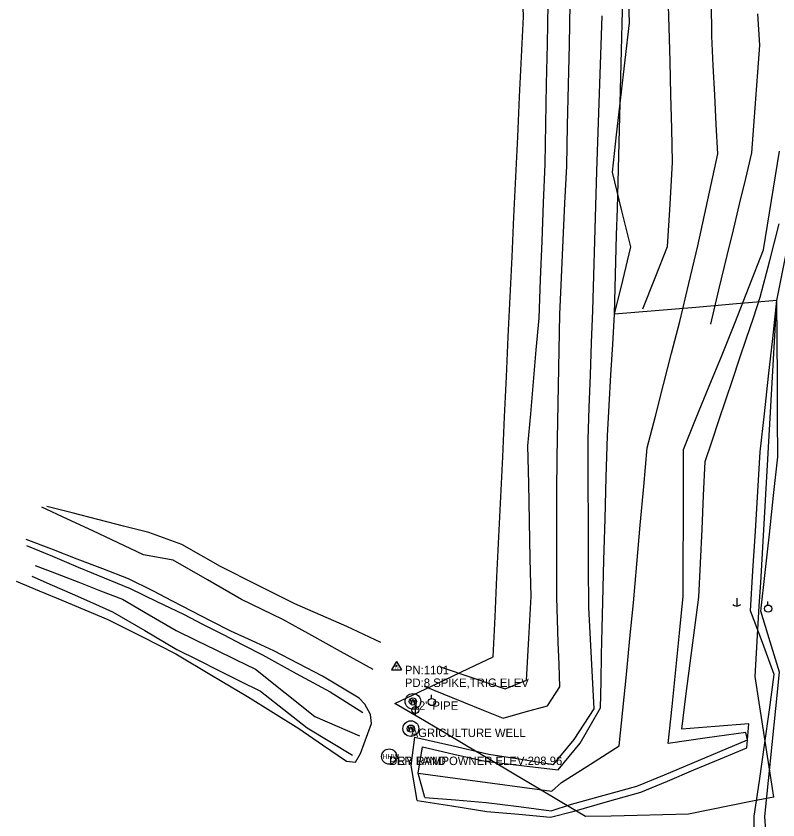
# Model space of a CAD drawing. Extents: x 1445297 to 1476720, y 2042269 to 2057889.
# Drawn here: x 1445590.2 to 1446040.2, y 2043652.1 to 2044126.9 of the extents above; entities that cross this region are included whole.
import ezdxf

# ---------------------------------------------------------------- set-up
doc = ezdxf.new("R2010")
doc.units = 0
for name, color, linetype in [('S_DITCHLINE', 7, 'Continuous'), ('S_HIST_HIGH_WATER', 7, 'Continuous'), ('S_HIST_HIGH_WATER_ANNOT', 7, 'Continuous'), ('S_LEVEE', 7, 'Continuous'), ('S_MSC_PT_SYM', 7, 'Continuous'), ('S_SECONDARY_CTL', 7, 'Continuous'), ('S_SECONDARY_CTL_ANNOT', 7, 'Continuous'), ('S_STREAM', 7, 'Continuous'), ('S_SURVEY_TEXT_ANNOT', 7, 'Continuous'), ('S_TREE', 7, 'Continuous'), ('S_UTILITY_POLE', 7, 'Continuous'), ('S_WATER_WELL', 7, 'Continuous'), ('S_WATER_WELL_ANNOT', 7, 'Continuous')]:
    doc.layers.add(name, color=color, linetype=linetype)

msp = doc.modelspace()

# ---------------------------------------------------------------- linework, layer by layer
at = {"layer": 'S_DITCHLINE'}
for points in [[(1445827.69, 2043679.83), (1445830.33, 2043695.34), (1445848.79, 2043691.06), (1445867.26, 2043686.78), (1445888.82, 2043684.29), (1445910.38, 2043681.81), (1445923.37, 2043697.42), (1445935.37, 2043718.28), (1445935.72, 2043733.97), (1445936.07, 2043749.66), (1445936.43, 2043765.35), (1445936.78, 2043781.04), (1445937.44, 2043805.54), (1445938.1, 2043830.04), (1445938.76, 2043854.55), (1445939.42, 2043879.05), (1445940.49, 2043897), (1445941.57, 2043914.95), (1445942.64, 2043932.89), (1445943.72, 2043950.84), (1445948.51, 2043970.73), (1445953.3, 2043990.62), (1445947.85, 2044012.67), (1445942.4, 2044034.72), (1445944.91, 2044056.79), (1445947.42, 2044078.86), (1445949.94, 2044100.93), (1445952.45, 2044123.01), (1445951.88, 2044142.3)], [(1445960.32, 2043954.05), (1445967.67, 2043972.41), (1445975.02, 2043990.77), (1445976.51, 2044015.71), (1445977.99, 2044040.65), (1445977.49, 2044060.52), (1445976.98, 2044080.39), (1445976.47, 2044100.26), (1445975.96, 2044120.13), (1445975.37, 2044139.62)], [(1445831.67, 2043665.49), (1445827.69, 2043679.83), (1445849.61, 2043676.85), (1445871.52, 2043673.88), (1445889.05, 2043671.5), (1445906.58, 2043669.13), (1445912.33, 2043674.35), (1445929.4, 2043685.12), (1445946.46, 2043695.88), (1445948.55, 2043717), (1445950.64, 2043738.12), (1445952.74, 2043759.23), (1445954.83, 2043780.35), (1445956.86, 2043803.25), (1445958.89, 2043826.15), (1445960.92, 2043849.05), (1445962.95, 2043871.95), (1445967.77, 2043890.61), (1445972.59, 2043909.26), (1445977.4, 2043927.92), (1445982.22, 2043946.58), (1445987.57, 2043968.95), (1445992.91, 2043991.31), (1445995.86, 2044004.88), (1445998.81, 2044018.46), (1446001.76, 2044032.03), (1446004.71, 2044045.61), (1446003.79, 2044062.98), (1446002.88, 2044080.35), (1446001.96, 2044097.73), (1446001.05, 2044115.1), (1446000.88, 2044135.29)], [(1446000.49, 2043944.87), (1446005.35, 2043965.2), (1446010.22, 2043985.52), (1446013.88, 2044000.7), (1446017.53, 2044015.88), (1446021.19, 2044031.07), (1446024.85, 2044046.25), (1446025.99, 2044062.11), (1446027.13, 2044077.98), (1446028.26, 2044093.84), (1446029.4, 2044109.71), (1446028.22, 2044128.31)], [(1445831.67, 2043665.49), (1445849.75, 2043663.95), (1445867.83, 2043662.41), (1445887.05, 2043660), (1445906.27, 2043657.58), (1445918.25, 2043661.45), (1445937.59, 2043666.73), (1445956.93, 2043672), (1445973.25, 2043678.84), (1445989.58, 2043685.68), (1446005.9, 2043692.52), (1446022.22, 2043699.36), (1446021.26, 2043703.84), (1445998.34, 2043700.61), (1445975.43, 2043697.38), (1445977.63, 2043719.09), (1445979.84, 2043740.81), (1445982.05, 2043762.52), (1445984.25, 2043784.23), (1445984.28, 2043805.93), (1445984.31, 2043827.62), (1445984.34, 2043849.32), (1445984.37, 2043871.01), (1445991.98, 2043889.64), (1445999.59, 2043908.26), (1446007.2, 2043926.88), (1446014.81, 2043945.51), (1446023.19, 2043967.15), (1446031.57, 2043988.78), (1446033.93, 2044003.39), (1446036.29, 2044018), (1446038.65, 2044032.61), (1446041.01, 2044047.21)], [(1446033.44, 2043639.99), (1446032.52, 2043654.08), (1446034.68, 2043675.4), (1446036.84, 2043696.72), (1446039, 2043718.04), (1446041.15, 2043739.36), (1446035.65, 2043757.41), (1446030.16, 2043775.47), (1446032.65, 2043798.24), (1446035.14, 2043821.02), (1446037.63, 2043843.79), (1446040.13, 2043866.56), (1446040, 2043889.64), (1446039.87, 2043912.72), (1446039.74, 2043935.8), (1446039.61, 2043958.89), (1446043.86, 2043980.65), (1446048.11, 2044002.41), (1446052.36, 2044024.17), (1446056.6, 2044045.93)], [(1446026.41, 2043640.96), (1446026.24, 2043654.4), (1446029.2, 2043675.31), (1446032.15, 2043696.22), (1446035.1, 2043717.12), (1446038.05, 2043738.03), (1446030.99, 2043756.87), (1446023.94, 2043775.71), (1446025.39, 2043799.19), (1446026.84, 2043822.66), (1446028.3, 2043846.14), (1446029.75, 2043869.62), (1446032.22, 2043891.93), (1446034.68, 2043914.25), (1446037.15, 2043936.57), (1446039.61, 2043958.89)], [(1445596.38, 2043814.2), (1445611.68, 2043807.84), (1445626.97, 2043801.48), (1445642.27, 2043795.12), (1445657.57, 2043788.76), (1445673.35, 2043781.2), (1445689.14, 2043773.64), (1445700.8, 2043767.63), (1445712.47, 2043761.61), (1445724.13, 2043755.59), (1445735.8, 2043749.58), (1445755.72, 2043738.7), (1445775.65, 2043727.83), (1445795.03, 2043715.5)], [(1445601.55, 2043802.51), (1445614.4, 2043797.5), (1445627.26, 2043792.48), (1445640.11, 2043787.47), (1445652.97, 2043782.45), (1445668.82, 2043773.25), (1445684.67, 2043764.04), (1445696.41, 2043758.34), (1445708.14, 2043752.64), (1445719.88, 2043746.94), (1445731.61, 2043741.24), (1445749.14, 2043727.28), (1445766.67, 2043713.32), (1445779.82, 2043707.56), (1445792.96, 2043701.8)], [(1445599.52, 2043796.13), (1445611.44, 2043790.87), (1445623.36, 2043785.6), (1445635.28, 2043780.33), (1445647.19, 2043775.07), (1445666.17, 2043763.96), (1445685.14, 2043752.86), (1445697.51, 2043746.68), (1445709.89, 2043740.5), (1445722.26, 2043734.32), (1445734.64, 2043728.13), (1445748.35, 2043717.3), (1445762.06, 2043706.46), (1445775.47, 2043698.4), (1445788.89, 2043690.34)]]:
    msp.add_lwpolyline(points, dxfattribs=at)
at = {"layer": 'S_HIST_HIGH_WATER'}
msp.add_circle((1445810.61, 2043689.55), 4.5, dxfattribs=at)
at = {"layer": 'S_LEVEE'}
for points in [[(1445831.19, 2043731.22), (1445842.85, 2043726.47), (1445854.51, 2043721.72), (1445866.17, 2043716.97), (1445877.83, 2043712.22), (1445890.92, 2043715.91), (1445904.01, 2043719.6), (1445911.39, 2043730.69), (1445910.92, 2043743.9), (1445910.45, 2043757.11), (1445909.98, 2043770.32), (1445909.52, 2043783.52), (1445909.57, 2043804.27), (1445909.63, 2043825.01), (1445909.68, 2043845.75), (1445909.74, 2043866.5), (1445910.13, 2043887.55), (1445910.52, 2043908.6), (1445910.92, 2043929.65), (1445911.31, 2043950.7), (1445912.33, 2043972.6), (1445913.36, 2043994.49), (1445914.38, 2044016.39), (1445915.4, 2044038.28), (1445915.93, 2044062.25), (1445916.46, 2044086.22), (1445916.99, 2044110.19), (1445917.52, 2044134.16)], [(1445840.59, 2043742.55), (1445859.88, 2043736.07), (1445879.16, 2043729.6), (1445891.77, 2043734.64), (1445893.06, 2043759.36), (1445894.35, 2043784.08), (1445893.89, 2043806.31), (1445893.43, 2043828.54), (1445892.97, 2043850.77), (1445892.51, 2043873), (1445894.17, 2043891.9), (1445895.83, 2043910.8), (1445897.48, 2043929.7), (1445899.14, 2043948.59), (1445900.02, 2043971.28), (1445900.9, 2043993.97), (1445901.78, 2044016.67), (1445902.66, 2044039.36), (1445903.12, 2044063.02), (1445903.58, 2044086.69), (1445904.04, 2044110.36), (1445904.5, 2044134.03)], [(1445801.16, 2043741.07), (1445781.83, 2043751.69), (1445764.84, 2043761.11), (1445747.84, 2043770.53), (1445735.61, 2043776.48), (1445723.38, 2043782.43), (1445703.22, 2043794.02), (1445683.06, 2043805.61), (1445665.52, 2043808.79), (1445650.51, 2043815.79), (1445635.5, 2043822.8), (1445620.49, 2043829.8), (1445605.47, 2043836.8)], [(1445805.68, 2043757.03), (1445785.63, 2043766.3), (1445770.23, 2043773), (1445754.83, 2043779.69), (1445732.89, 2043790.76), (1445710.94, 2043801.82), (1445699.52, 2043808.31), (1445688.09, 2043814.79), (1445668.65, 2043821.86), (1445653.56, 2043825.73), (1445638.47, 2043829.59), (1445623.38, 2043833.46), (1445608.3, 2043837.32)]]:
    msp.add_lwpolyline(points, dxfattribs=at)
at = {"layer": 'S_MSC_PT_SYM'}
msp.add_lwpolyline([(1445810.6, 2043689.54), (1445810.6, 2043689.59), (1445810.6, 2043689.54), (1445810.55, 2043689.54), (1445810.6, 2043689.54), (1445810.6, 2043689.49), (1445810.6, 2043689.54), (1445810.65, 2043689.54)], dxfattribs=at)
at = {"layer": 'S_SECONDARY_CTL'}
for p, q in [((1445814.86, 2043745.78), (1445811.85, 2043740.83)), ((1445814.86, 2043745.78), (1445817.81, 2043740.83)), ((1445811.85, 2043740.83), (1445817.81, 2043740.83))]:
    msp.add_line(p, q, dxfattribs=at)
for radius in [0.311, 0.183, 0.103]:
    msp.add_circle((1445814.86, 2043743.17), radius, dxfattribs=at)
at = {"layer": 'S_STREAM'}
for points in [[(1445827.14, 2043663.69), (1445823.54, 2043684.29), (1445825.8, 2043700.97), (1445847.6, 2043696.01), (1445869.4, 2043691.05), (1445888.55, 2043687.94), (1445907.7, 2043684.84), (1445919.75, 2043699.57), (1445931.57, 2043717.75), (1445930.79, 2043732.69), (1445930, 2043747.64), (1445929.21, 2043762.58), (1445928.43, 2043777.53), (1445928.33, 2043802.33), (1445928.23, 2043827.12), (1445928.13, 2043851.92), (1445928.04, 2043876.72), (1445928.72, 2043895.81), (1445929.41, 2043914.89), (1445930.1, 2043933.98), (1445930.79, 2043953.07), (1445931.38, 2043973.65), (1445931.97, 2043994.23), (1445932.56, 2044014.81), (1445933.15, 2044035.39), (1445933.94, 2044058.29), (1445934.74, 2044081.2), (1445935.53, 2044104.1), (1445936.33, 2044127)], [(1445827.14, 2043663.69), (1445847.67, 2043660.46), (1445868.2, 2043657.22), (1445887.06, 2043655.48), (1445905.91, 2043653.74), (1445919.75, 2043657.39), (1445939.51, 2043662.95), (1445959.27, 2043668.52), (1445974.92, 2043675.08), (1445990.57, 2043681.64), (1446006.22, 2043688.2), (1446021.87, 2043694.76), (1446023.04, 2043708.81), (1446003.18, 2043707.29), (1445983.33, 2043705.76), (1445985.87, 2043725.26), (1445988.42, 2043744.76), (1445990.96, 2043764.26), (1445993.5, 2043783.77), (1445994.42, 2043803.79), (1445995.34, 2043823.81), (1445996.27, 2043843.83), (1445997.19, 2043863.85), (1446001.26, 2043875.99), (1446005.33, 2043888.12), (1446009.4, 2043900.26), (1446013.46, 2043912.39), (1446017.53, 2043924.52), (1446021.6, 2043936.66), (1446025.67, 2043948.79), (1446029.74, 2043960.92), (1446035.35, 2043982.6), (1446040.97, 2044004.27)], [(1445590.2, 2043793.15), (1445603.75, 2043787.51), (1445617.3, 2043781.88), (1445630.85, 2043776.24), (1445644.4, 2043770.61), (1445664.5, 2043760.41), (1445684.61, 2043750.2), (1445705.72, 2043737.62), (1445726.82, 2043725.03), (1445742.01, 2043715.55), (1445757.2, 2043706.06), (1445771.23, 2043696.48), (1445785.27, 2043686.89), (1445790.7, 2043686.27), (1445793.58, 2043691.38), (1445800.09, 2043709.06), (1445799.59, 2043714.44), (1445796.22, 2043720.52), (1445792.82, 2043723.99), (1445782, 2043730.57), (1445771.18, 2043737.14), (1445756.85, 2043744.57), (1445742.52, 2043752), (1445729.73, 2043757.83), (1445716.95, 2043763.66), (1445705.47, 2043769.59), (1445693.99, 2043775.52), (1445682.51, 2043781.44), (1445671.04, 2043787.37), (1445656.66, 2043794.59), (1445641.52, 2043800.39), (1445626.38, 2043806.19), (1445611.24, 2043812), (1445596.1, 2043817.8)]]:
    msp.add_lwpolyline(points, dxfattribs=at)
at = {"layer": 'S_TREE'}
for points in [[(1446037.75, 2043665.67), (1446025.16, 2043663.13), (1446012.57, 2043660.59), (1445999.98, 2043658.05), (1445987.39, 2043655.51), (1445972.18, 2043655.16), (1445956.98, 2043654.81), (1445941.77, 2043654.46), (1445926.56, 2043654.11), (1445912.49, 2043662.47), (1445898.41, 2043670.83), (1445884.34, 2043679.2), (1445870.26, 2043687.56), (1445856.18, 2043695.92), (1445842.11, 2043704.29), (1445828.03, 2043712.65), (1445813.95, 2043721.01), (1445828.47, 2043727.86), (1445842.99, 2043734.71), (1445857.51, 2043741.57), (1445872.02, 2043748.42), (1445873.14, 2043772.04), (1445874.25, 2043795.67), (1445875.37, 2043819.29), (1445876.48, 2043842.91), (1445877.6, 2043866.54), (1445878.71, 2043890.16), (1445879.83, 2043913.79), (1445880.94, 2043937.41), (1445882.06, 2043961.03), (1445883.17, 2043984.66), (1445884.28, 2044008.28), (1445885.4, 2044031.91), (1445886.51, 2044055.53), (1445887.63, 2044079.16), (1445888.74, 2044102.78), (1445889.86, 2044126.4), (1445889.19, 2044149.14)], [(1446037.75, 2043665.67), (1446035, 2043683.44), (1446032.26, 2043701.22), (1446029.52, 2043719), (1446026.78, 2043736.77), (1446027.58, 2043750.66), (1446028.38, 2043764.54), (1446029.19, 2043778.42), (1446029.99, 2043792.3), (1446030.79, 2043806.18), (1446031.59, 2043820.07), (1446032.4, 2043833.95), (1446033.2, 2043847.83), (1446034, 2043861.71), (1446034.8, 2043875.59), (1446035.6, 2043889.48), (1446036.41, 2043903.36), (1446037.21, 2043917.24), (1446038.01, 2043931.12), (1446038.81, 2043945), (1446039.61, 2043958.89), (1446015.64, 2043956.87), (1445991.67, 2043954.86), (1445967.69, 2043952.85), (1445943.72, 2043950.84), (1445944.12, 2043966.43), (1445944.52, 2043982.01), (1445944.93, 2043997.6), (1445945.33, 2044013.18), (1445945.73, 2044028.76), (1445946.13, 2044044.35), (1445946.54, 2044059.93), (1445946.94, 2044075.52), (1445947.34, 2044091.1), (1445947.74, 2044106.68), (1445948.15, 2044122.27), (1445948.55, 2044137.85)]]:
    msp.add_lwpolyline(points, dxfattribs=at)
at = {"layer": 'S_UTILITY_POLE'}
for p, q in [((1446015.81, 2043783.2), (1446015.81, 2043778.47)), ((1446034.28, 2043779.07), (1446034.28, 2043781.18)), ((1445835.63, 2043723.93), (1445835.63, 2043726.03)), ((1445826.03, 2043714.09), (1445826.03, 2043719.88))]:
    msp.add_line(p, q, dxfattribs=at)
for centre, radius in [((1446034.41, 2043776.93), 2.13), ((1445835.75, 2043721.78), 2.13), ((1445826.03, 2043717.02), 2.05)]:
    msp.add_circle(centre, radius, dxfattribs=at)
msp.add_arc((1446015.87, 2043781.9), 3.41, 226.3972, 313.6028, dxfattribs=at)
at = {"layer": 'S_WATER_WELL'}
for p, q in [((1445823.04, 2043723.41), (1445823.7, 2043720.93)), ((1445823.7, 2043720.93), (1445824.51, 2043723.41)), ((1445824.51, 2043723.41), (1445825.56, 2043720.93)), ((1445825.56, 2043720.93), (1445826.14, 2043723.45)), ((1445821.8, 2043707.33), (1445822.46, 2043704.85)), ((1445822.46, 2043704.85), (1445823.27, 2043707.33)), ((1445823.27, 2043707.33), (1445824.32, 2043704.85)), ((1445824.32, 2043704.85), (1445824.9, 2043707.37))]:
    msp.add_line(p, q, dxfattribs=at)
for centre, radius in [((1445824.6, 2043722.15), 4.63), ((1445824.57, 2043722.15), 2.13), ((1445823.36, 2043706.07), 4.63), ((1445823.33, 2043706.07), 2.13)]:
    msp.add_circle(centre, radius, dxfattribs=at)

# ---------------------------------------------------------------- texts
at = {"layer": 'S_HIST_HIGH_WATER'}
msp.add_text('HHW', height=3, dxfattribs=at).set_placement((1445806.52, 2043688.05))
at = {"layer": 'S_HIST_HIGH_WATER_ANNOT'}
msp.add_text('PER LAND OWNER ELEV:208.96', height=5, dxfattribs=at).set_placement((1445810.61, 2043684.55))
at = {"layer": 'S_SECONDARY_CTL'}
msp.add_text('TV', height=1.5, dxfattribs=at).set_placement((1445813.65, 2043741.16))
at = {"layer": 'S_SECONDARY_CTL_ANNOT'}
for s, p in [('PN:1101', (1445819.86, 2043738.17)), ('PD:8 SPIKE,TRIG ELEV', (1445819.86, 2043730.67))]:
    msp.add_text(s, height=5, dxfattribs=at).set_placement(p)
at = {"layer": 'S_SURVEY_TEXT_ANNOT'}
msp.add_text('DRY RAMP', height=5, dxfattribs=at).set_placement((1445810.6, 2043684.54))
at = {"layer": 'S_WATER_WELL_ANNOT'}
for s, p in [('12" PIPE', (1445824.45, 2043717.18)), ('AGRICULTURE WELL', (1445823.21, 2043701.1))]:
    msp.add_text(s, height=5, dxfattribs=at).set_placement(p)

doc.saveas('drawing.dxf')
